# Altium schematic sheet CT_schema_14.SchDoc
size 388 x 278 mm
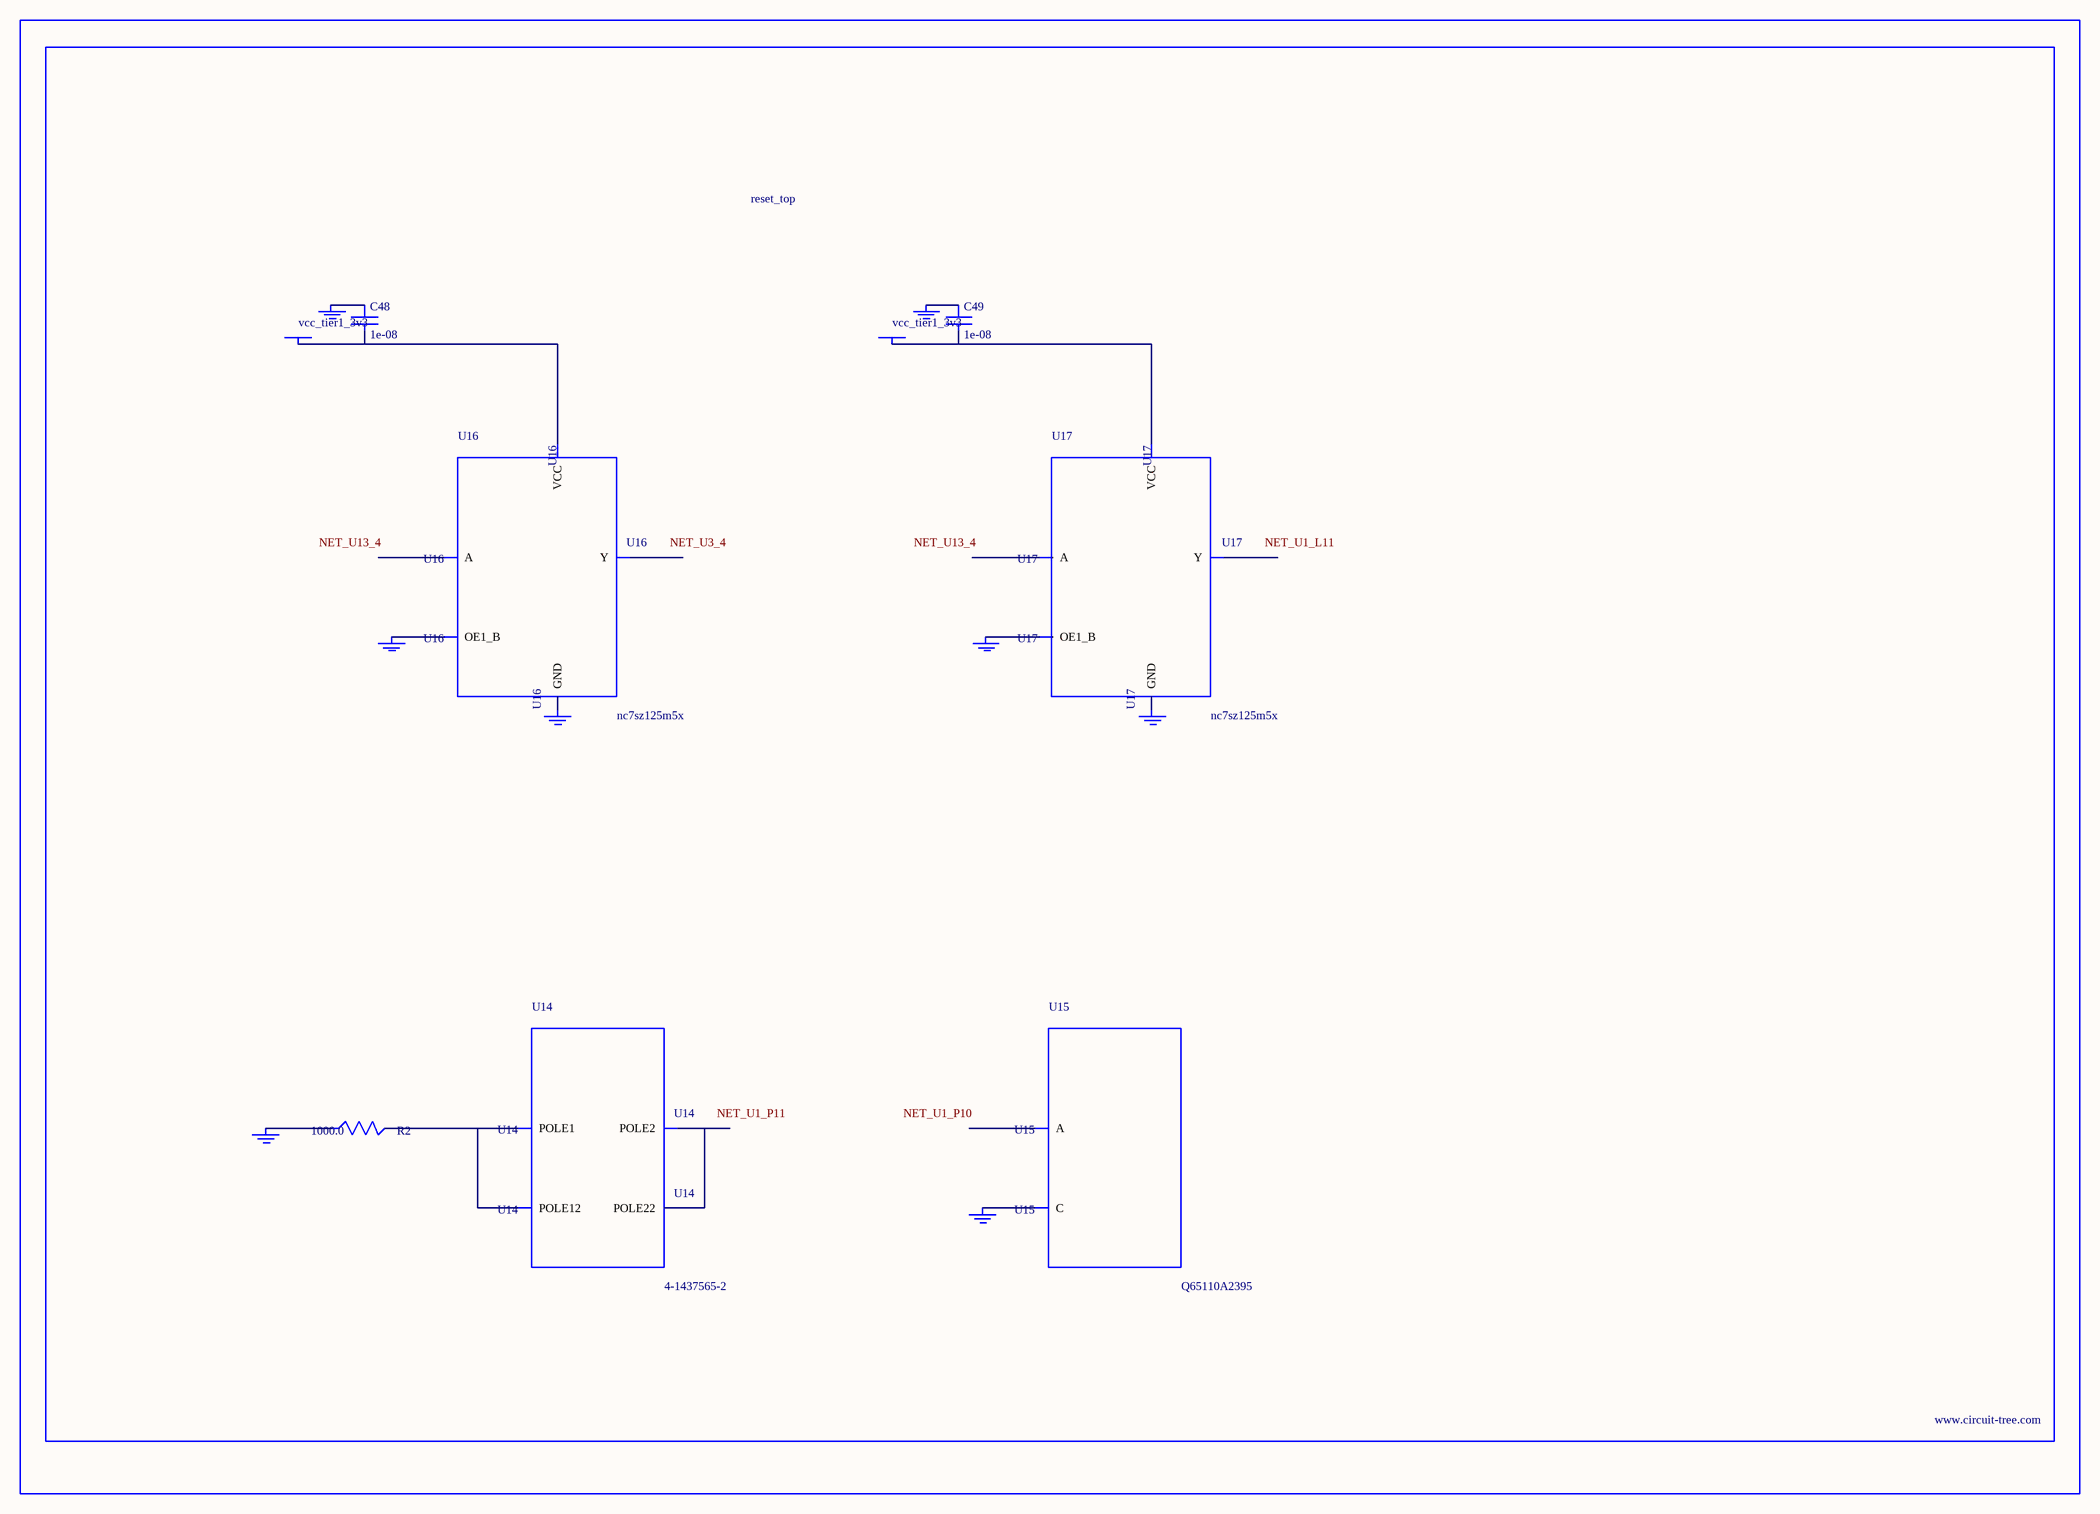
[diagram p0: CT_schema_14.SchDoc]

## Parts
BORDER13  (no value)
C48  1e-08  [C0402]
C49  1e-08  [C0402]
GND_INSTANCE_13_0  (no value)
GND_INSTANCE_13_1  (no value)
GND_INSTANCE_13_2  (no value)
GND_INSTANCE_13_3  (no value)
GND_INSTANCE_13_4  (no value)
GND_INSTANCE_13_5  (no value)
GND_INSTANCE_13_6  (no value)
GND_INSTANCE_13_7  (no value)
POWER_INSTANCE_13_0  vcc_tier1_3v3
POWER_INSTANCE_13_1  vcc_tier1_3v3
R2  1000.0  [R0603]
U14  4-1437565-2  [SW_4-1437565-2]
U15  Q65110A2395  [LGM67K-G1J2-24-Z]
U16  nc7sz125m5x  [NC7SZ125M5X]
U17  nc7sz125m5x  [NC7SZ125M5X]

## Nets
NetC48_1: C48.1 GND_INSTANCE_13_2.0(GND)
NetC48_2: C48.2 POWER_INSTANCE_13_0.0(PWR) U16.5(VCC)
NetC49_1: C49.1 GND_INSTANCE_13_5.0(GND)
NetC49_2: C49.2 POWER_INSTANCE_13_1.0(PWR) U17.5(VCC)
NetGND_INSTANCE_13_0_0: GND_INSTANCE_13_0.0(GND) R2.1
NetGND_INSTANCE_13_1_0: GND_INSTANCE_13_1.0(GND) U15.C
NetGND_INSTANCE_13_3_0: GND_INSTANCE_13_3.0(GND) U16.1(OE1_B)
NetGND_INSTANCE_13_4_0: GND_INSTANCE_13_4.0(GND) U16.3(GND)
NetGND_INSTANCE_13_6_0: GND_INSTANCE_13_6.0(GND) U17.1(OE1_B)
NetGND_INSTANCE_13_7_0: GND_INSTANCE_13_7.0(GND) U17.3(GND)
NetR2_2: R2.2 U14.1(POLE1) U14.2(POLE12)
NetU14_3: U14.3(POLE2) U14.4(POLE22)

Not connected (* = marked no-connect by the designer): U15 A; U16 2(A) 4(Y); U17 2(A) 4(Y)

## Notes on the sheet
- Labels drawn without touching a wire or pin: NET_U1_L11, NET_U1_P10, NET_U1_P11, NET_U3_4, NET_U13_4

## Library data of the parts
BORDER13 = BORDER_PAGE13
C48 C49 = C0402C103K3RAC
GND_INSTANCE_13_0-GND_INSTANCE_13_7 = GND
POWER_INSTANCE_13_0 POWER_INSTANCE_13_1 = PWR
R2 = RC0603JR-071KL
